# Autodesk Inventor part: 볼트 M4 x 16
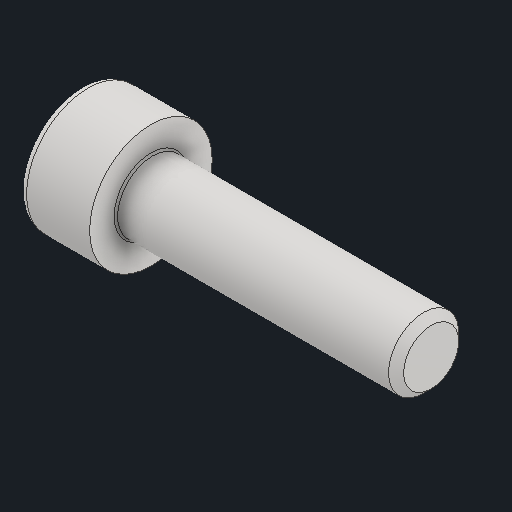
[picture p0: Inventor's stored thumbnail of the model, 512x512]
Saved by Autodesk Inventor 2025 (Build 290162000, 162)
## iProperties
Created: 2025-08
Part Number: 볼트 M4 x 16
Material: 스테인리스강
Description: 6각 소켓 머리 캡 나사
Document SubType Name: Modeling
Designer: infra006
Density: 8.08 g/cm^3
Appearance: 기본값
Author: jhkim
Sending System: Autodesk Inventor 2026
Preprocessor: ST-DEVELOPER v20.1
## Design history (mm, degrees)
feature "Solid1"
node "솔리드1"
